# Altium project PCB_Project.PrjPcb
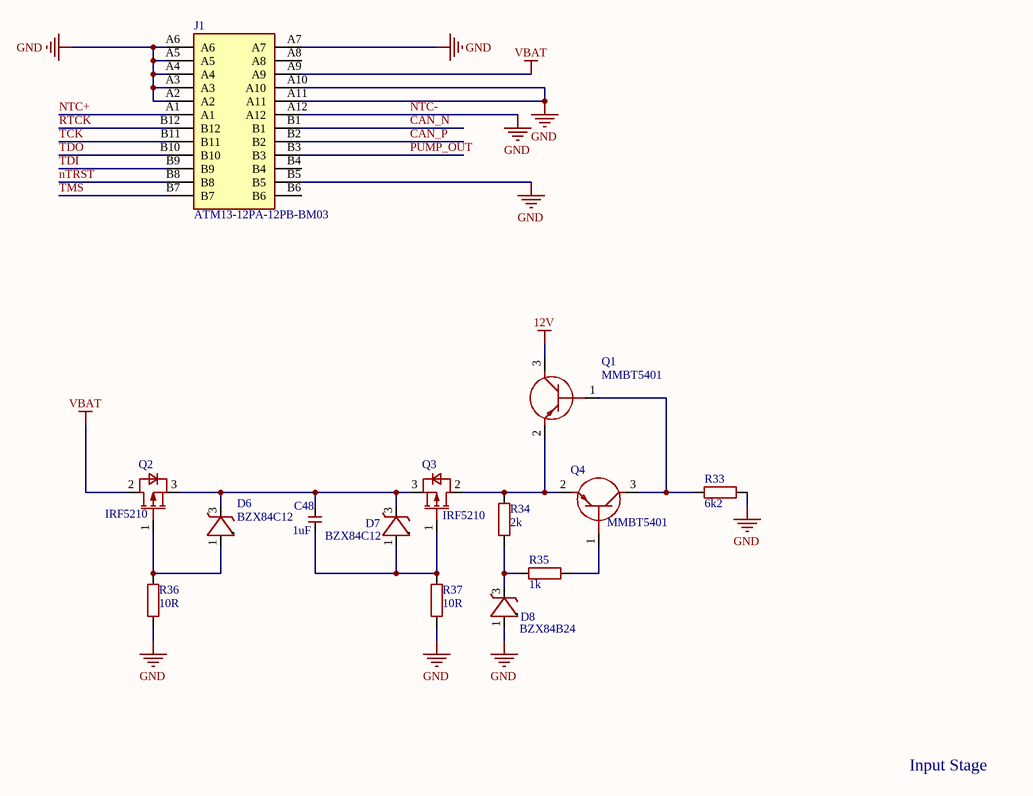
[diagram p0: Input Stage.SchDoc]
6 sheets, 125 parts. Net scope: global (net labels, ports and power ports of the same name join across sheets).
Board file: PCB1.PcbDoc
Sheets:
  Input Stage.SchDoc
  Power Supply.SchDoc
  Microcontroller.SchDoc
  Pump Driver.SchDoc
  Shunt.SchDoc
  NTC.SchDoc

## Sheet Input Stage.SchDoc
size A4; SheetNumber: 1; SheetTotal: 4

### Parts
C48  1uF  [C0402]
D6  BZX84C12  [SOT96P237X111-3N]
D7  BZX84C12  [SOT96P237X111-3N]
D8  BZX84B24  [TRANS_BZX84_ROM-M]
J1  ATM13-12PA-12PB-BM03  [ATM1312PA12PBBM03]
Q1  MMBT5401  [SOT95P240X120-3N]
Q2  IRF5210  [TO254P1528X508-4_3N-V1]
Q3  IRF5210  [TO254P1528X508-4_3N-V1]
Q4  MMBT5401  [SOT95P240X120-3N]
R33  6k2  [R0402]
R34  2k  [R0402]
R35  1k  [R0402]
R36  10R  [R0402]
R37  10R  [R0402]

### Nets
12V: Q1.3(C)
GND: D8.1(A) J1.A2 J1.A3 J1.A4 J1.A5 J1.A6 J1.A7 J1.A10 J1.A11 J1.A12 J1.B5 R33.2 R36.1 R37.1
VBAT: J1.A9 Q2.2(DRAIN)
CAN_N: J1.B1
CAN_P: J1.B2
NTC+: J1.A1
nTRST: J1.B8
PUMP_OUT: J1.B3
RTCK: J1.B12
TCK: J1.B11
TDI: J1.B9
TDO: J1.B10
TMS: J1.B7
NetC48_1: C48.1 D7.1(A) Q3.1(GATE) R37.2
NetC48_2: C48.2 D6.3(K) D7.3(K) Q2.3(SOURCE) Q3.3(SOURCE)
NetD6_1: D6.1(A) Q2.1(GATE) R36.2
NetD8_3: D8.3(K) R34.1 R35.1
NetQ1_1: Q1.1(B) Q4.3(C) R33.1
NetQ1_2: Q1.2(E) Q3.2(DRAIN) Q4.2(E) R34.2
NetQ4_1: Q4.1(B) R35.2

Not connected (* = marked no-connect by the designer): D6 2(NC); D7 2(NC); D8 2(NC); J1 A8 B4 B6

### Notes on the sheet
- NTC-
- Input Stage

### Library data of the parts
C48 = C0402C105K4PAC7411: Ceramic Capacitor, Multilayer, Ceramic, 16V, 10% +Tol, 10% -Tol, X5R, 15% TC, 1uF, Surface Mount, 0402; Manufacturer: KEMET; Multilayer: Yes
D6 D7 = BZX84C12LT1G: Zener Diode, 12V V(Z), 5.39%, 0.25W, Silicon, Unidirectional, TO-236AB; Manufacturer: ON Semiconductor; Package Body Material: Plastic; Dynamic Impedance-Max: 25R; Number of Elements: 1; Max Power Dissipation: 250mW; Test Current: 5mA; Additional Feature: UL RECOGNIZED; Time @ Peak Reflow Temperature-Max (s): 40s; Qualification Status: Not Qualified
D8 = BZX84B24VLFHT116: Zener Diode, 24V V(Z), 2.08%, 0.25W, Silicon, Unidirectional
J1 = ATM13-12PA-12PB-BM03: AMPHENOL SINE/TUCHEL - ATM13-12PA-12PB-BM03 - ATM HEADER  (2) 12 POSITION SIZE 20, A&B KEY  - TIN PLATING 98AC7190; Geometry.Height: 35.4mm
Q1 Q4 = MMBT5401: Small Signal Bipolar Transistor, 0.6A I(C), 150V V(BR)CEO, 1-Element, PNP, Silicon, TO-236; Manufacturer: Diotec; Package Body Material: Plastic; Max Collector Current: 600mA; DC Current Gain-Min (hFE): 50; Number of Elements: 1; Frequency: 100MHz; Qualification Status: Not Qualified
Q2 Q3 = IRF5210STRLPBF: Zener Diode, 24V V(Z), 2.08%, 0.25W, Silicon, Unidirectional; Manufacturer: Infineon; Package Body Material: Plastic; Polarity/Channel Type: P-CHANNEL; Avalanche Energy Rating (Eas): 120mJ; Case Connection: DRAIN; Drain Current-Max (ID): 38A; Drain-source On Resistance-Max: 60mR; DS Breakdown Voltage-Min: 100V; FET Technology: METAL-OXIDE SEMICONDUCTOR; Number of Elements: 1; Operating Mode: ENHANCEMENT MODE; Pulsed Drain Current-Max (IDM): 140A; Transistor Application: SWITCHING; Time @ Peak Reflow Temperature-Max (s): 30s; Power Dissipation-Max (Abs): 170W; JEDEC-95 Code: TO-263AB; Qualification Status: Not Qualified
R33 = AC0402FR-076K2L: Fixed Resistor, Metal Glaze/thick Film, 0.0625W, 6200ohm, 50V, 1% +/-Tol, 100ppm/Cel, Surface Mount, 0402; Manufacturer: Yageo; Additional Feature: LASER TRIMMABLE; Power: 62.5mW; Rated Temperature: 70°C; Value: 6.2kR; Temperature Coefficient (ppm/Cel): 100; Package Height: 0.32mm; Package Length: 1mm; Package Width: 0.5mm; Reference Standard: AEC-Q200
R34 = RC0402JR-072KP: Fixed Resistor, Metal Glaze/thick Film, 0.0625W, 2000ohm, 50V, 5% +/-Tol, 150ppm/Cel, Surface Mount, 0402; Manufacturer: Yageo
R35 = RT0402FRE101KL: Fixed Resistor, Thin Film, 0.0625W, 1000ohm, 50V, 1% +/-Tol, 50ppm/Cel, Surface Mount, 0402; Manufacturer: Yageo
R36 R37 = AC0402FR-1010RL: Fixed Resistor, Metal Glaze/thick Film, 0.0625W, 10ohm, 50V, 1% +/-Tol, 200ppm/Cel, Surface Mount, 0402; Manufacturer: Yageo; Additional Feature: LASER TRIMMABLE; Power: 62.5mW; Rated Temperature: 70°C; Temperature Coefficient (ppm/Cel): 200; Package Height: 0.32mm; Package Length: 1mm; Package Width: 0.5mm; Reference Standard: AEC-Q200

## Sheet Power Supply.SchDoc
size A4; SheetNumber: 2; SheetTotal: 4
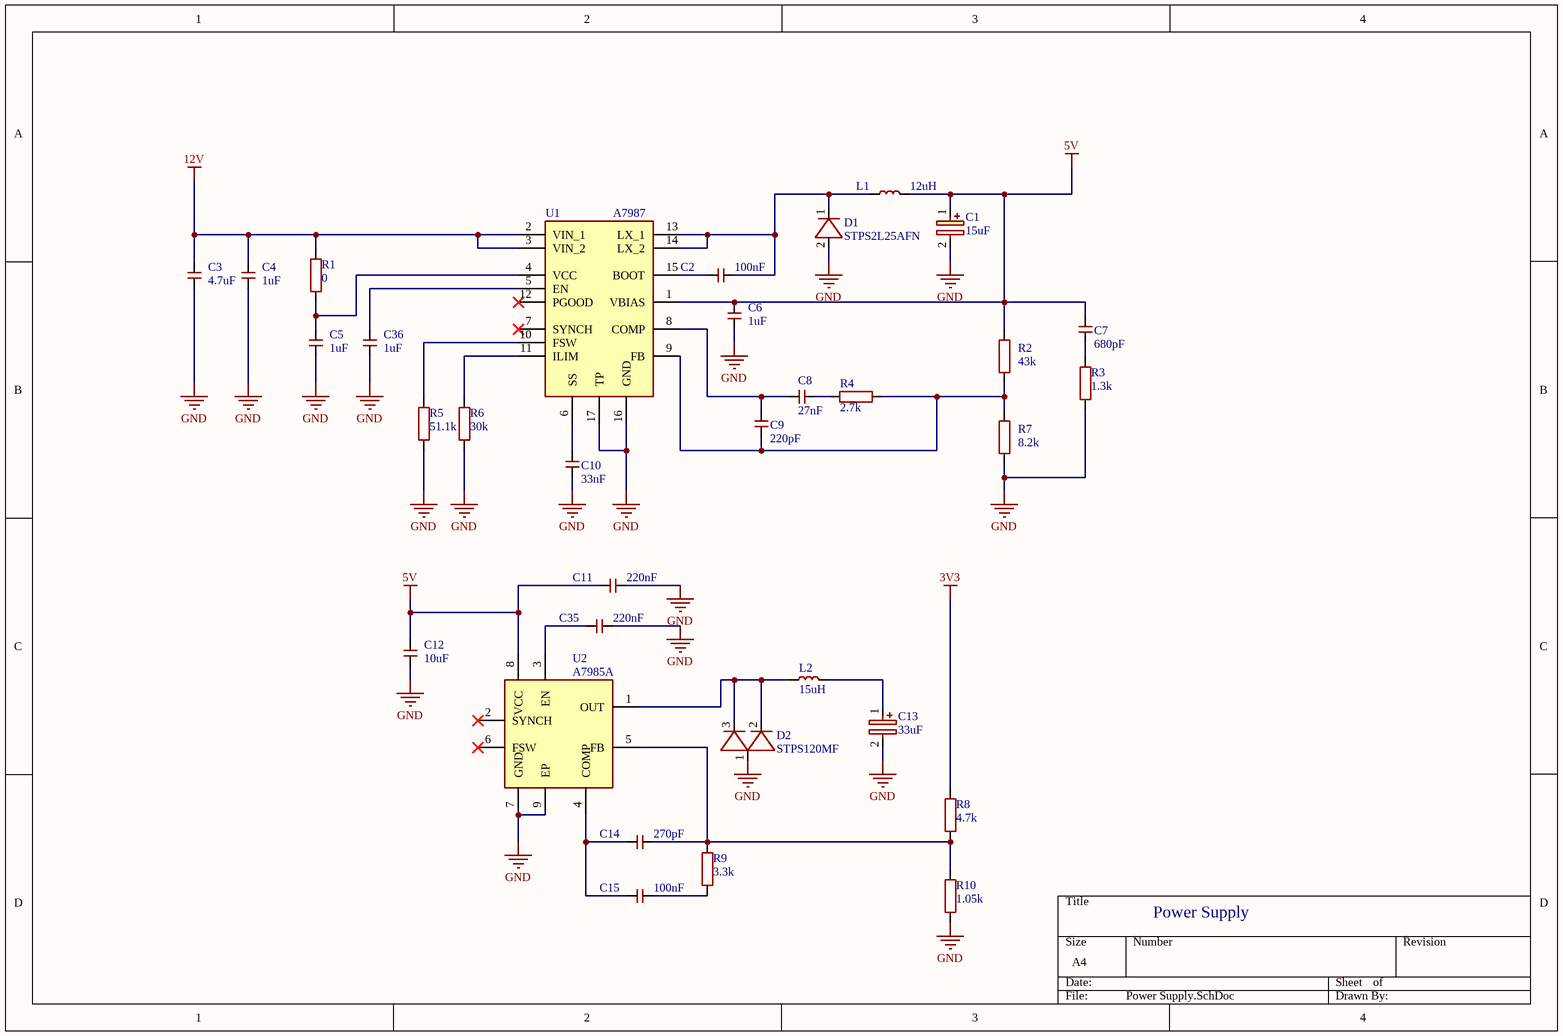
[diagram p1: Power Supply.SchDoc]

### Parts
C1  15uF  [CAPAE660X850N]
C2  100nF  [C0402]
C3  4.7uF  [CAPC3216X180N]
C4  1uF  [C0402]
C5  1uF  [C0402]
C6  1uF  [C0402]
C7  680pF  [C0402]
C8  27nF  [C0402]
C9  220pF  [C0402]
C10  33nF  [C0402]
C11  220nF  [C0402]
C12  10uF  [CAPC2012X145N]
C13  33uF  [10SVPS10M]
C14  270pF  [C0402]
C15  100nF  [C0402]
C35  220nF  [C0402]
C36  1uF  [C0402]
D1  STPS2L25AFN  [SODFL5226X110N]
D2  STPS120MF  [STPS120MF]
L1  12uH  [WE-PD2_105455]
L2  15uH  [INDPM6868X420N]
R1  0  [R0402]
R2  43k  [R0402]
R3  1.3k  [R0402]
R4  2.7k  [R0402]
R5  51.1k  [R0402]
R6  30k  [R0402]
R7  8.2k  [R0402]
R8  4.7k  [R0402]
R9  3.3k  [R0402]
R10  1.05k  [R0402]
U1  A7987  [SOP65P640X120-17N]
U2  A7985A  [SOIC127P600X170-9N]

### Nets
3V3: R8.2
5V: C1.1(+) C6.1 C7.2 C11.1 C12.2 L1.2 R2.2 U1.1(VBIAS) U2.8(VCC)
12V: C3.2 C4.2 R1.2 U1.2(VIN_1) U1.3(VIN_2)
GND: C1.2 C3.1 C4.1 C5.1 C6.2 C10.1 C11.2 C12.1 C13.2 C35.2 C36.1 D1.2(A) D2.1(A) R3.1 R5.1 R6.1 R7.1 R10.1 U1.16(GND) U1.17(TP) U2.7(GND) U2.9(EP)
NetC2_1: C2.1 U1.15(BOOT)
NetC2_2: C2.2 D1.1(K) L1.1 U1.13(LX_1) U1.14(LX_2)
NetC5_2: C5.2 R1.1 U1.4(VCC)
NetC7_1: C7.1 R3.2
NetC8_1: C8.1 C9.2 U1.8(COMP)
NetC8_2: C8.2 R4.1
NetC9_1: C9.1 R2.1 R4.2 R7.2 U1.9(FB)
NetC10_2: C10.2 U1.6(SS)
NetC13_1: C13.1(+) L2.2
NetC14_1: C14.1 C15.1 U2.4(COMP)
NetC14_2: C14.2 R8.1 R9.2 R10.2 U2.5(FB)
NetC15_2: C15.2 R9.1
NetC35_1: C35.1 U2.3(EN)
NetC36_2: C36.2 U1.5(EN)
NetD2_2: D2.2(K) D2.3(K) L2.1 U2.1(OUT)
NetR5_2: R5.2 U1.10(FSW)
NetR6_2: R6.2 U1.11(ILIM)

Not connected (* = marked no-connect by the designer): U1 7(SYNCH)* 12(PGOOD)*; U2 2(SYNCH)* 6(FSW)*

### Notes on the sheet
- Power Supply

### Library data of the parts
C1 = AHA0608150M050R: Hybrid Aluminum V-Chip, 15uF, 50V ¦ AVX AHA0608150M050R; Manufacturer: Kyocera AVX
C2 C15 = C0402C104K3PACTU: Ceramic Capacitor, Multilayer, Ceramic, 25V, 10% +Tol, 10% -Tol, X5R, 15% TC, 0.1uF, Surface Mount, 0402; Manufacturer: KEMET; Multilayer: Yes
C3 = EMK316BJ475MLHT: Ceramic Capacitor, Multilayer, Ceramic, 16V, 20% +Tol, 20% -Tol, X5R, 15% TC, 4.7uF, Surface Mount, 1206; Manufacturer: Taiyo Yuden
C4-C6 C36 = C0402C105K4PAC7411: as C48 on sheet Input Stage
C7 = C0402C681K8RACTU: Ceramic Capacitor, Multilayer, Ceramic, 10V, 10% +Tol, 10% -Tol, X7R, 15% TC, 0.00068uF, Surface Mount, 0402; Manufacturer: KEMET; Multilayer: Yes
C8 = C0402C273K4RALTU: .027Uf 16.0V Rohs Compliant: No; Manufacturer: KEMET
C9 = C0402S221K5RACAUTO: Ceramic Capacitor, Multilayer, Ceramic, 50V, 10% +Tol, 10% -Tol, X7R, 15% TC, 0.00022uF, Surface Mount, 0402; Manufacturer: KEMET
C10 = C0402C333M4REC7411: Ceramic Capacitor, Multilayer, Ceramic, 16V, 20% +Tol, 20% -Tol, X7R, 15% TC, 0.033uF, Surface Mount, 0402; Manufacturer: KEMET
C11 C35 = C0402C224K9PAC7411: Ceramic Capacitor, Multilayer, Ceramic, 6.3V, 10% +Tol, 10% -Tol, X5R, 15% TC, 0.22uF, Surface Mount, 0402; Manufacturer: KEMET; Multilayer: Yes
C12 = GRM21BR60J106KE19L: Ceramic Capacitor, Multilayer, Ceramic, 6.3V, 10% +Tol, 10% -Tol, X5R, 15% TC, 10uF, Surface Mount, 0805; Manufacturer: Murata; Multilayer: Yes
C13 = 4SVP33M: Aluminum Electrolytic Capacitor, Polarized, Aluminum (solid Polymer), 4V, 20% +Tol, 20% -Tol, 33uF, Surface Mount, 1717; Manufacturer: Panasonic; Manufacturer Series: SVP; Dielectric Material: Aluminium; ESR (Equivalent Series Resistance): 200mR; Leakage Current: 66uA; Ripple Current: 37mA; Tan Delta: 0.15
C14 = C0402C271J5GAC7411: Ceramic Capacitor, Multilayer, Ceramic, 50V, 5% +Tol, 5% -Tol, C0G, 30ppm/Cel TC, 0.00027uF, Surface Mount, 0402; Manufacturer: KEMET; Multilayer: Yes
D1 = STPS2L25AFN: Rectifier Diode; Manufacturer: STMicroelectronics
D2 = STPS120MF: Rectifier Diode, Schottky, 1 Phase, 1 Element, 1A, 20V V(RRM), Silicon, DO-222AA; Manufacturer: STMicroelectronics; Package Body Material: Plastic; Case Connection: CATHODE; Forward Voltage: 410mV; Non-rep Pk Forward Current-Max: 50A; Number of Elements: 1; Qualification Status: Not Qualified
L1 = 744776112: General Purpose Inductor, 12uH, 20%, 1 Element, Nickel-zinc Ferrite-Core, SMD, 3935; Manufacturer: Wurth Electronics; DC Resistance (DCR): 70mR; Inductor Application: POWER INDUCTOR; Channels: 1; Max Current Rating: 2.72A; Shape/Size Description: RECTANGULAR PACKAGE; Shielding: Unshielded; Test Frequency: 1kHz; Self Resonant Frequency: 20MHz
L2 = SRR6838A-150M: Power Inductors - SMD Ind,6.8x6.8x3.8mm,15uH+/-20%,2.1A,; Manufacturer: Bourns
R1 = AC0402JR-7D0RL: Fixed Resistor, Metal Glaze/thick Film, 0.0625W, 0ohm, Surface Mount, 0402; Manufacturer: Yageo
R2 = AF0402FR-0743KL: Fixed Resistor, Metal Glaze/thick Film, 0.0625W, 43000ohm, 50V, 1% +/-Tol, 100ppm/Cel, Surface Mount, 0402; Manufacturer: Yageo; Additional Feature: ANTI-SULFUR; Power: 62.5mW; Rated Temperature: 70°C; Value: 43kR; Temperature Coefficient (ppm/Cel): 100; Package Height: 0.32mm; Package Length: 1mm; Package Width: 0.5mm; Reference Standard: AEC-Q200
R3 = AT0402DRD071K3L: Fixed Resistor, Thin Film, 0.0625W, 1300ohm, 50V, 0.5% +/-Tol, 25ppm/Cel, Surface Mount, 0402; Manufacturer: Yageo; Additional Feature: HIGH PRECISION; Power: 62.5mW; Rated Temperature: 70°C; Value: 1.3kR; Temperature Coefficient (ppm/Cel): 25; Package Height: 0.3mm; Package Length: 1mm; Package Width: 0.5mm; Reference Standard: AEC-Q200
R4 = AC0402FR-072K7L: Fixed Resistor, Metal Glaze/thick Film, 0.0625W, 2700ohm, 50V, 1% +/-Tol, 100ppm/Cel, Surface Mount, 0402; Manufacturer: Yageo; Additional Feature: LASER TRIMMABLE; Power: 62.5mW; Rated Temperature: 70°C; Value: 2.7kR; Temperature Coefficient (ppm/Cel): 100; Package Height: 0.32mm; Package Length: 1mm; Package Width: 0.5mm; Reference Standard: AEC-Q200
R5 = RT0402BRE0751K1L: Fixed Resistor, Thin Film, 0.0625W, 51100ohm, 50V, 0.1% +/-Tol, 50ppm/Cel, Surface Mount, 0402; Manufacturer: Yageo; Additional Feature: HIGH PRECISION; Power: 62.5mW; Rated Temperature: 70°C; Value: 51.1kR; Temperature Coefficient (ppm/Cel): 50; Package Height: 0.3mm; Package Length: 1mm; Package Width: 0.5mm
R6 = RC0402FR-1330KL: Fixed Resistor, Metal Glaze/thick Film, 0.0625W, 30000ohm, 50V, 1% +/-Tol, 100ppm/Cel, Surface Mount, 0402; Manufacturer: Yageo; Additional Feature: LASER TRIMMABLE; Power: 62.5mW; Rated Temperature: 70°C; Value: 30kR; Temperature Coefficient (ppm/Cel): 100; Package Height: 0.35mm; Package Length: 1mm; Package Width: 0.5mm
R7 = RC0402BR-078K2L: Fixed Resistor, Metal Glaze/thick Film, 0.0625W, 8200ohm, 50V, 0.1% +/-Tol, 100ppm/Cel, Surface Mount, 0402; Manufacturer: Yageo
R8 = RC0402FR-7W4K7L: Fixed Resistor, Metal Glaze/thick Film, 0.125W, 4700ohm, 50V, 1% +/-Tol, 200ppm/Cel, Surface Mount, 0402; Manufacturer: Yageo; Additional Feature: LASER TRIMMABLE; Power: 125mW; Rated Temperature: 70°C; Value: 4.7kR; Temperature Coefficient (ppm/Cel): 200; Package Height: 0.35mm; Package Length: 1mm; Package Width: 0.5mm
R9 = RC0402FR-7D3K3L: Fixed Resistor, Metal Glaze/thick Film, 0.0625W, 3300ohm, 50V, 1% +/-Tol, 100ppm/Cel, Surface Mount, 0402; Manufacturer: Yageo; Additional Feature: LASER TRIMMABLE; Power: 62.5mW; Rated Temperature: 70°C; Value: 3.3kR; Temperature Coefficient (ppm/Cel): 100; Package Height: 0.35mm; Package Length: 1mm; Package Width: 0.5mm
R10 = AC0402FR-071K05L: Fixed Resistor, Metal Glaze/thick Film, 0.0625W, 1050ohm, 50V, 1% +/-Tol, 100ppm/Cel, Surface Mount, 0402; Manufacturer: Yageo; Additional Feature: LASER TRIMMABLE; Power: 62.5mW; Rated Temperature: 70°C; Value: 1.05kR; Temperature Coefficient (ppm/Cel): 100; Package Height: 0.32mm; Package Length: 1mm; Package Width: 0.5mm; Reference Standard: AEC-Q200
U1 = A7987TR: Switching Regulator, Voltage-mode, 4.4A, 1650kHz Switching Freq-Max, PDSO16; Manufacturer: STMicroelectronics
U2 = A7985ATR: Switching Regulator, Voltage-mode, 3.5A, 275kHz Switching Freq-Max, PDSO8; Manufacturer: STMicroelectronics; Package Body Material: Plastic; Package Equivalence Code: SOP8,.25; Control Technique: PULSE WIDTH MODULATION; Max Supply Voltage: 38V; Min Input Voltage: 4.5V; Nominal Supply Voltage: 12V; Channels: 1; Switcher Configuration: BUCK; Qualification Status: Not Qualified

## Sheet Microcontroller.SchDoc
size A4; SheetNumber: 3; SheetTotal: 4
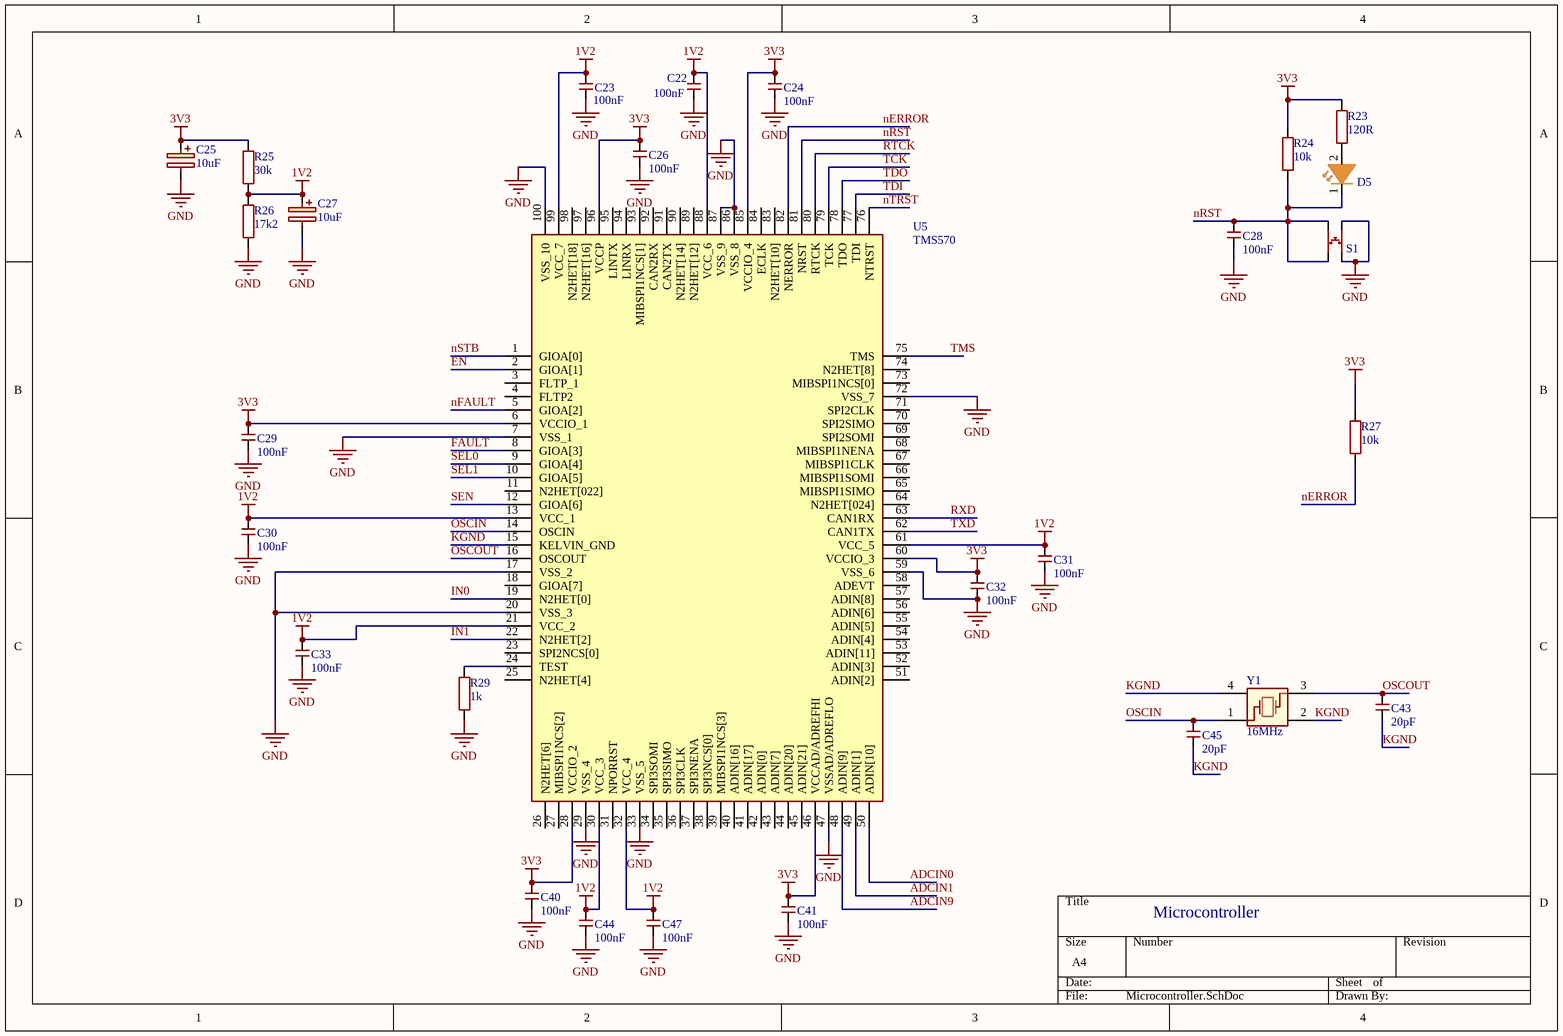
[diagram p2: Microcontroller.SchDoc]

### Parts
C22  100nF  [C0402]
C23  100nF  [C0402]
C24  100nF  [C0402]
C25  10uF  [CAPAE660X565N]
C26  100nF  [C0402]
C27  10uF  [CAPAE660X565N]
C28  100nF  [C0402]
C29  100nF  [C0402]
C30  100nF  [C0402]
C31  100nF  [C0402]
C32  100nF  [C0402]
C33  100nF  [C0402]
C40  100nF  [C0402]
C41  100nF  [C0402]
C43  20pF  [C0402]
C44  100nF  [C0402]
C45  20pF  [C0402]
C47  100nF  [C0402]
D5  150060AS75000  [LED-0603]  (value not drawn)
R23  120R  [R0402]
R24  10k  [R0402]
R25  30k  [R0402]
R26  17k2  [R0402]
R27  10k  [R0402]
R29  1k  [R0402]
S1  Pushbutton  [Pushbutton]  (value not drawn)
U5  TMS570  [QFP50P1600X1600X160-100N]
Y1  16MHz  [ECS1601037B2CTNTR]

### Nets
1V2: C22.2 C23.2 C27.1(+) C30.2 C31.2 C33.2 C44.2 C47.2 R25.1 R26.2 U5.13(VCC_1) U5.21(VCC_2) U5.30(VCC_3) U5.32(VCC_4) U5.61(VCC_5) U5.88(VCC_6) U5.99(VCC_7)
3V3: C24.2 C25.1(+) C26.2 C29.2 C32.2 C40.2 C41.2 R23.2 R24.2 R25.2 R27.2 U5.6(VCCIO_1) U5.28(VCCIO_2) U5.46(VCCAD/ADREFHI) U5.60(VCCIO_3) U5.85(VCCIO_4) U5.96(VCCP)
GND: C22.1 C23.1 C24.1 C25.2 C26.1 C27.2 C28.1 C29.1 C30.1 C31.1 C32.1 C33.1 C40.1 C41.1 C44.1 C47.1 R26.1 R29.1 S1.1 S1.2 U5.7(VSS_1) U5.17(VSS_2) U5.20(VSS_3) U5.29(VSS_4) U5.33(VSS_5) U5.47(VSSAD/ADREFLO) U5.59(VSS_6) U5.72(VSS_7) U5.86(VSS_8) U5.87(VSS_9) U5.100(VSS_10)
ADCIN0: U5.50(ADIN[10])
ADCIN1: U5.49(ADIN[1])
ADCIN9: U5.48(ADIN[9])
EN: U5.2(GIOA[1])
~{FAULT}: U5.8(GIOA[3])
IN0: U5.19(N2HET[0])
IN1: U5.22(N2HET[2])
KGND: C43.1 C45.1 U5.15(KELVIN_GND) Y1.2 Y1.4
nERROR: R27.1 U5.82(NERROR)
nFAULT: U5.5(GIOA[2])
nRST: C28.2 D5.1(K) R24.1 S1.3 S1.4 U5.81(NRST)
nSTB: U5.1(GIOA[0])
nTRST: U5.76(NTRST)
OSCIN: C45.2 U5.14(OSCIN) Y1.1
OSCOUT: C43.2 U5.16(OSCOUT) Y1.3
RTCK: U5.80(RTCK)
RXD: U5.63(CAN1RX)
SEL0: U5.9(GIOA[4])
SEL1: U5.10(GIOA[5])
SEN: U5.12(GIOA[6])
TCK: U5.79(TCK)
TDI: U5.77(TDI)
TDO: U5.78(TDO)
TMS: U5.75(TMS)
TXD: U5.62(CAN1TX)
NetD5_2: D5.2(A) R23.1
NetR29_2: R29.2 U5.24(TEST)

Not connected (* = marked no-connect by the designer): U5 3(FLTP_1) 4(FLTP2) 11(N2HET[022]) 18(GIOA[7]) 23(SPI2NCS[0]) 25(N2HET[4]) 26(N2HET[6]) 27(MIBSPI1NCS[2]) 31(NPORRST) 34(SPI3SOMI) 35(SPI3SIMO) 36(SPI3CLK) 37(SPI3NENA) 38(SPI3NCS[0]) 39(MIBSPI1NCS[3]) 40(ADIN[16]) 41(ADIN[17]) 42(ADIN[0]) 43(ADIN[7]) 44(ADIN[20]) 45(ADIN[21]) 51(ADIN[2]) 52(ADIN[3]) 53(ADIN[11]) 54(ADIN[4]) 55(ADIN[5]) 56(ADIN[6]) 57(ADIN[8]) 58(ADEVT) 64(N2HET[024]) 65(MIBSPI1SIMO) 66(MIBSPI1SOMI) 67(MIBSPI1CLK) 68(MIBSPI1NENA) 69(SPI2SOMI) 70(SPI2SIMO) 71(SPI2CLK) 73(MIBSPI1NCS[0]) 74(N2HET[8]) 83(N2HET[10]) 84(ECLK) 89(N2HET[12]) 90(N2HET[14]) 91(CAN2TX) 92(CAN2RX) 93(MIBSPI1NCS[1]) 94(LINRX) 95(LINTX) 97(N2HET[16]) 98(N2HET[18])

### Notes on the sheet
- Microcontroller

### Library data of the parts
C22-C24 C26 C28-C33 C40 C41 C44 C47 = C0402C104K3PACTU: as C2 on sheet Power Supply
C25 C27 = EXV106M050A9GAA: Aluminum Electrolytic Capacitor, Polarized, Aluminum (wet), 50V, 20% +Tol, 20% -Tol, 10uF, Surface Mount, 2626; Manufacturer: KEMET; Dielectric Material: Aluminium; ESR (Equivalent Series Resistance): 2.6R; Leakage Current: 5uA; Ripple Current: 98mA; Tan Delta: 0.12
C43 C45 = C0402C200F5GACTU: Ceramic Capacitor, Multilayer, Ceramic, 50V, 1% +Tol, 1% -Tol, C0G, 30ppm/Cel TC, 0.00002uF, Surface Mount, 0402; Manufacturer: KEMET; Multilayer: Yes
D5 = 150060AS75000: Single Color LED, Amber, Water Clear, 1.1mm; Manufacturer: Wurth Electronics
R23 = AC0402FR-7D120RL: Fixed Resistor, Metal Glaze/thick Film, 0.0625W, 120ohm, 50V, 1% +/-Tol, -100,100ppm/Cel, 0402; Manufacturer: Yageo; Power: 62.5mW; Package Height: 0.32mm; Package Length: 1mm; Package Width: 0.5mm; Reference Standard: AEC-Q200
R24 R27 = RP0402BRD0710KL: Resistor, 10K, 0.1%, 0.063W, THIN FILM, 0402;; Manufacturer: Yageo
R25 = RC0402FR-1330KL: as R6 on sheet Power Supply
R26 = TNPW040217K2BEED: Fixed Resistor, Thin Film, 0.063W, 17200ohm, 50V, 0.1% +/-Tol, 25ppm/Cel, Surface Mount, 0402; Manufacturer: Vishay Dale; Manufacturer Series: TNPW; Power: 63mW; Rated Temperature: 70°C; Value: 17.2kR; Temperature Coefficient (ppm/Cel): 25
R29 = RT0402FRE101KL: as R35 on sheet Input Stage
S1 = Pushbutton: BUTON MINI 6X6X5, 4 PINI
U5 = TMS5700332BPZQQ1: RISC Microcontroller, 32-Bit, FLASH, CORTEX-R4F CPU, 80MHz, CMOS, PQFP100; Manufacturer: Texas Instruments
Y1 = ECS-160-10-37B2-CTN-TR: Crystal 16MHz 10pF 4-Pin SMD ECX-1637B2 T/R; Manufacturer: ECS International

## Sheet Pump Driver.SchDoc
size A4; SheetNumber: 4; SheetTotal: 4
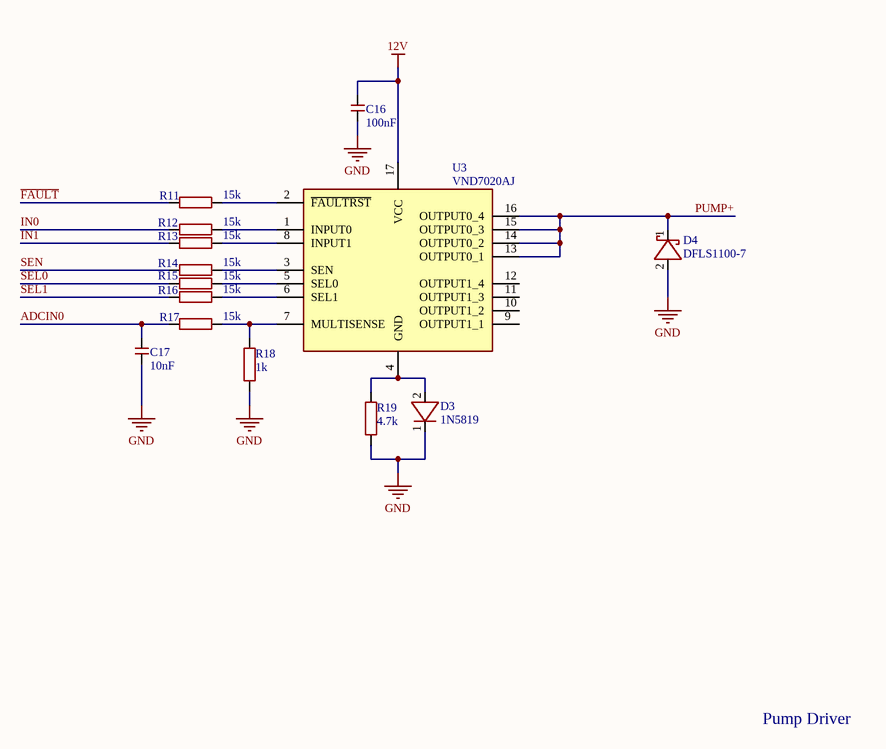
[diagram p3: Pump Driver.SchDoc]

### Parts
C16  100nF  [C0402]
C17  10nF  [C0402]
D3  1N5819  [SOD3716X125N]
D4  DFLS1100-7  [DFLS110]
R11  15k  [R0402]
R12  15k  [R0402]
R13  15k  [R0402]
R14  15k  [R0402]
R15  15k  [R0402]
R16  15k  [R0402]
R17  15k  [R0402]
R18  1k  [R0402]
R19  4.7k  [R0402]
U3  VND7020AJ  [SOP50P600X170-17N]

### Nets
12V: C16.2 U3.17(VCC)
GND: C16.1 C17.1 D3.1(K) D4.2(A) R18.1 R19.1
ADCIN0: C17.2 R17.1
~{FAULT}: R11.1
IN0: R12.1
IN1: R13.1
PUMP+: D4.1(K) U3.13(OUTPUT0_1) U3.14(OUTPUT0_2) U3.15(OUTPUT0_3) U3.16(OUTPUT0_4)
SEL0: R15.1
SEL1: R16.1
SEN: R14.1
NetD3_2: D3.2(A) R19.2 U3.4(GND)
NetR11_2: R11.2 U3.2(~{FAULTRST})
NetR12_2: R12.2 U3.1(INPUT0)
NetR13_2: R13.2 U3.8(INPUT1)
NetR14_2: R14.2 U3.3(SEN)
NetR15_2: R15.2 U3.5(SEL0)
NetR16_2: R16.2 U3.6(SEL1)
NetR17_2: R17.2 R18.2 U3.7(MULTISENSE)

Not connected (* = marked no-connect by the designer): U3 9(OUTPUT1_1) 10(OUTPUT1_2) 11(OUTPUT1_3) 12(OUTPUT1_4)

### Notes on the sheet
- Pump Driver

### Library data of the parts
C16 = C0402C104K3PACTU: as C2 on sheet Power Supply
C17 = C0402T103K4RALTU: Ceramic Capacitor, Multilayer, Ceramic, 16V, 10% +Tol, 10% -Tol, X7R, 15% TC, 0.01uF, Surface Mount, 0402; Manufacturer: KEMET; Multilayer: Yes
D3 = 1N5819HW-7-F: Rectifier Diode, Schottky, 1 Phase, 1 Element, 1A, 40V V(RRM), Silicon; Manufacturer: Diodes; Package Body Material: Plastic; Number of Elements: 1; Max Power Dissipation: 450mW; Forward Voltage: 320mV; Non-rep Pk Forward Current-Max: 25A; Time @ Peak Reflow Temperature-Max (s): 40s; Qualification Status: Not Qualified
D4 = DFLS1100-7: Rectifier Diode, Schottky, 1 Phase, 1 Element, 1A, 100V V(RRM), Silicon; Manufacturer: Diodes; Package Body Material: Plastic; Case Connection: CATHODE; Forward Voltage: 770mV; Non-rep Pk Forward Current-Max: 40A; Number of Elements: 1; Time @ Peak Reflow Temperature-Max (s): 40s; Qualification Status: Not Qualified
R11-R17 = AC0402JR-7W15KL: Chip Resistor Automotive Grade Thick Film 0402 15kOhm 5% Paper T/R; Manufacturer: Yageo
R18 = RT0402FRE101KL: as R35 on sheet Input Stage
R19 = RC0402FR-7W4K7L: as R8 on sheet Power Supply
U3 = VND7020AJTR: Buffer/Inverter Based Peripheral Driver, PDSO16; Manufacturer: STMicroelectronics; Package Body Material: Plastic; Built-in Protections: Over Current,Over Voltage,Under Voltage,TRANSIENT,THERMAL; Interface IC Type: BUFFER OR INVERTER BASED PERIPHERAL DRIVER; Channels: 1; Output Current Flow Direction: SINK; Max Supply Voltage: 28V; Min Supply Voltage: 4V; Nominal Supply Voltage: 13V; Turn-Off Delay Time: 100us; Turn-On Delay Time: 120us

## Sheet Shunt.SchDoc
size A4; SheetNumber: 5; SheetTotal: 5
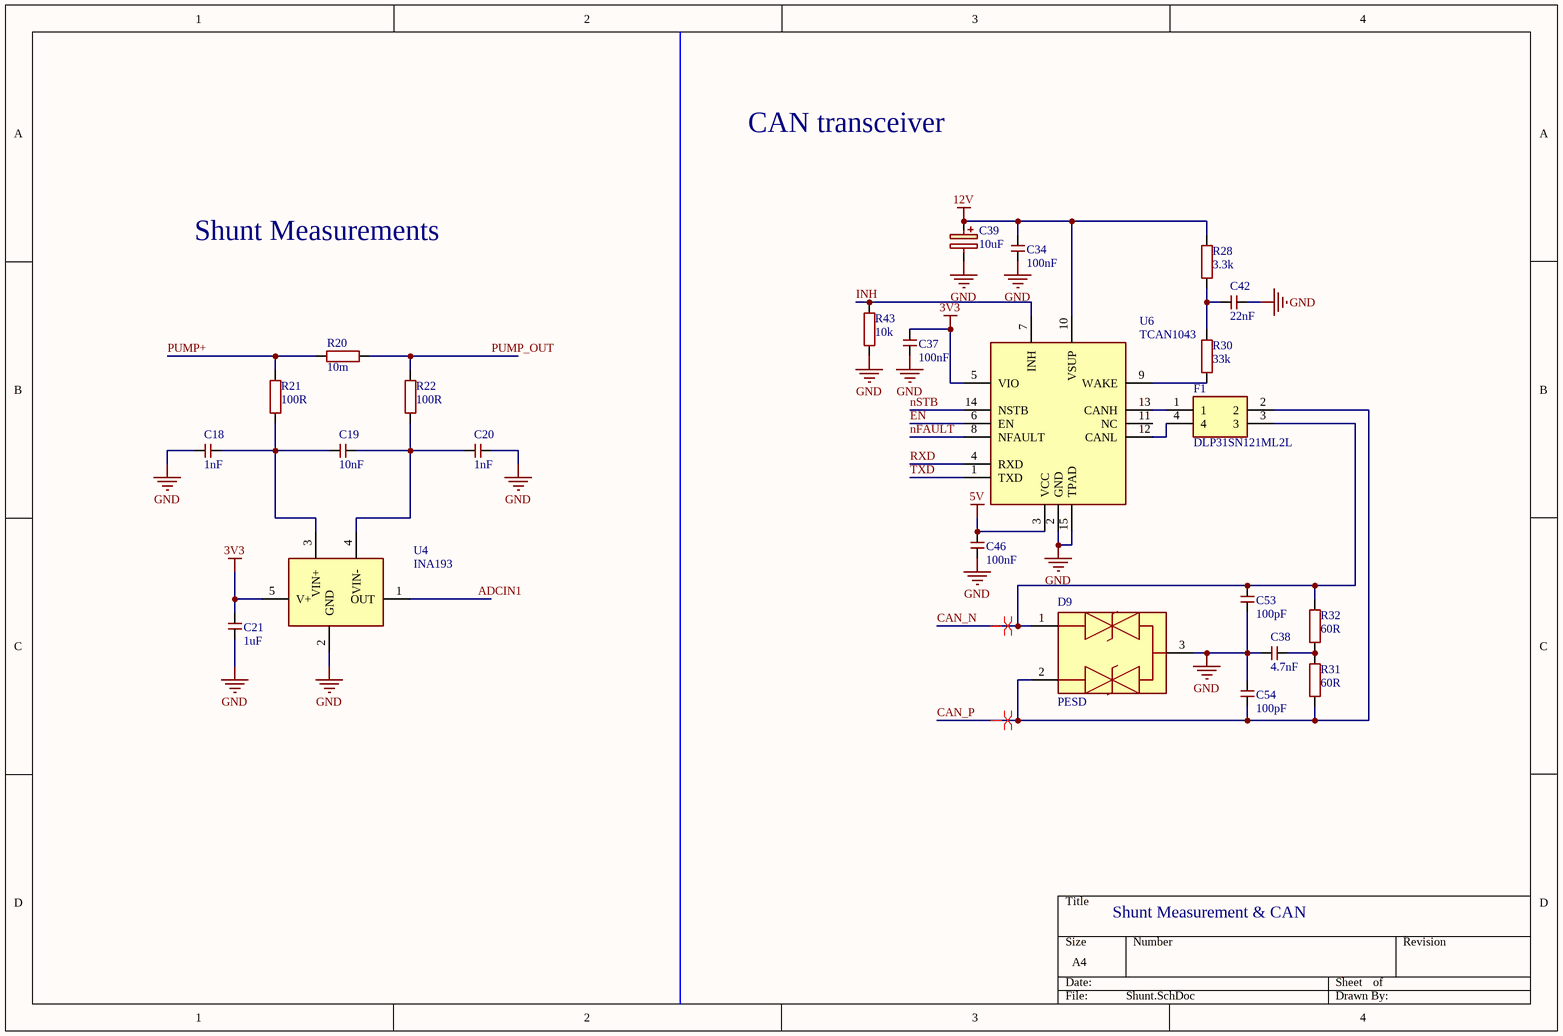
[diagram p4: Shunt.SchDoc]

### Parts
C18  1nF  [C0402]
C19  10nF  [C0402]
C20  1nF  [C0402]
C21  1uF  [C0402]
C34  100nF  [C0402]
C37  100nF  [C0402]
C38  4.7nF  [C0402]
C39  10uF  [CAPAE660X565N]
C42  22nF  [C0402]
C46  100nF  [C0402]
C53  100pF  [C0402]
C54  100pF  [C0402]
D9  PESD  [PESD2CANFD36LTQR]
F1  DLP31SN121ML2L  [DLP31SN121ML2B]
R20  10m  [CSS0402FT10L0]
R21  100R  [R0402]
R22  100R  [R0402]
R28  3.3k  [R0402]
R30  33k  [R0402]
R31  60R  [R0201]
R32  60R  [R0201]
R43  10k  [R0402]
U4  INA193  [SOT95P280X145-5N]
U6  TCAN1043  [SON65P300X450X90-15N]

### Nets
3V3: C21.2 C37.2 U4.5(V+) U6.5(VIO)
5V: C46.2 U6.3(VCC)
12V: C34.2 C39.1(+) R28.2 U6.10(VSUP)
GND: C18.1 C20.2 C21.1 C34.1 C37.1 C38.2 C39.2 C42.1 C46.1 C53.2 C54.1 D9.3(CC) R43.1 U4.2(GND) U6.2(GND) U6.15(TPAD)
ADCIN1: U4.1(OUT)
CAN_N: C53.1 D9.1(K1) F1.3 R32.1
CAN_P: C54.2 D9.2(K2) F1.2 R31.2
EN: U6.6(EN)
INH: R43.2 U6.7(INH)
nFAULT: U6.8(NFAULT)
nSTB: U6.14(NSTB)
PUMP+: R20.1 R21.2
PUMP_OUT: R20.2 R22.2
RXD: U6.4(RXD)
TXD: U6.1(TXD)
NetC18_2: C18.2 C19.1 R21.1 U4.3(VIN+)
NetC19_2: C19.2 C20.1 R22.1 U4.4(VIN-)
NetC38_1: C38.1 R31.1 R32.2
NetC42_2: C42.2 R28.1 R30.2
NetF1_1: F1.1 U6.13(CANH)
NetF1_4: F1.4 U6.12(CANL)
NetR30_1: R30.1 U6.9(WAKE)

Not connected (* = marked no-connect by the designer): U6 11(NC)

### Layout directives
differential pair: CAN_N, CAN_P

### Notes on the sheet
- CAN transceiver
- Shunt Measurements
- Shunt Measurement & CAN

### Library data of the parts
C18 C20 = C0402C102J5GACAUTO: Ceramic Capacitor, Multilayer, Ceramic, 50V, 5% +Tol, 5% -Tol, C0G, 30ppm/Cel TC, 0.001uF, Surface Mount, 0402; Manufacturer: KEMET; Multilayer: Yes; Reference Standard: AEC-Q200
C19 = C0402T103K4RALTU: as C17 on sheet Pump Driver
C21 = C0402C105K4PAC7411: as C48 on sheet Input Stage
C34 C37 C46 = C0402C104K3PACTU: as C2 on sheet Power Supply
C38 = C0402C472J4JACAUTO: Cap Ceramic 0.0047uF 16V U2J 5% Pad SMD 0402 125C T/R; Manufacturer: KEMET
C39 = EXV106M050A9GAA: as C25 on sheet Microcontroller
C42 = C0402C223J5RACTU: Ceramic Capacitor, Multilayer, Ceramic, 50V, 5% +Tol, 5% -Tol, X7R, 15% TC, 0.022uF, Surface Mount, 0402; Manufacturer: KEMET; Multilayer: Yes
C53 C54 = C0402C101K3RACAUTO: Multilayer Ceramic Capacitors MLCC - SMD/SMT 25V 100pF X7R 0402 10% AEC-Q200; Manufacturer: KEMET
D9 = PESD2CANFD36LT-QR: ESD Protection Diodes / TVS Diodes ESD protection for in-vehicle networks; Manufacturer: Nexperia
F1 = DLP31SN121ML2L: Data Line Filter, 2 Function(s), 16V, 0.1A, 4 Pin(s); Manufacturer: Murata; DC Resistance-Max: 2R; Insulation Resistance-Min: 100MR; Channels: 2; Output Impedance: 120R; Current Rating: 100mA
R20 = CSS0402FT10L0: Fixed Resistor, Metal Alloy, 0.33W, 0.01ohm, 1% +/-Tol, 100ppm/Cel, Surface Mount, 0402; Manufacturer: Stackpole Electronics
R21 R22 = RP0402DRD07100RL: Res, 100R, 0.5%, 0.063W, Thin Film, 0402 Rohs Compliant: Yes; Manufacturer: Yageo
R28 = RC0402FR-7D3K3L: as R9 on sheet Power Supply
R30 = RC0402FR-7D33KL: Fixed Resistor, Metal Glaze/thick Film, 0.0625W, 33000ohm, 50V, 1% +/-Tol, 100ppm/Cel, Surface Mount, 0402; Manufacturer: Yageo
R31 R32 = RK73H1HRTTCM60R4F: Fixed Resistor, Metal Glaze/thick Film, 0.05W, 60.4ohm, 25V, 1% +/-Tol, 300ppm/Cel, Surface Mount, 0201; Manufacturer: KOA Speer
R43 = RP0402BRD0710KL: as R24 on sheet Microcontroller
U4 = INA193AQDBVRQ1: Operational Amplifier, 1 Func, PDSO5; Manufacturer: Texas Instruments; Package Body Material: Plastic; Adjustable Threshold: No; Throw Configuration: POWER SUPPLY SUPPORT CIRCUIT; Number of Channels: 1; Package Equivalence Code: TSOP5/6,.11,37; Power Supplies: 12V; Supply Current-Max (Isup): 1.25mA; Max Supply Voltage: 18V; Min Supply Voltage: 2.7V; Qualification Status: Not Qualified
U6 = TCAN1043DMTRQ1: Ethernet Transceiver, 1-Trnsvr, PDSO14; Manufacturer: Texas Instruments

## Sheet NTC.SchDoc
size A4; SheetNumber: 6; SheetTotal: 6
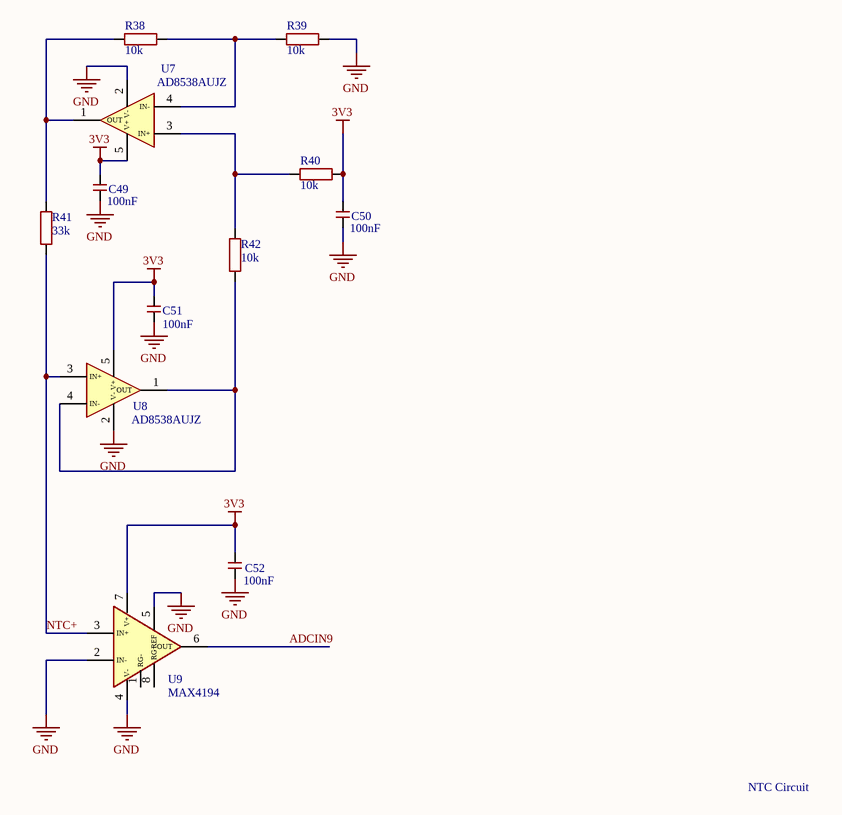
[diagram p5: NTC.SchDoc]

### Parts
C49  100nF  [C0402]
C50  100nF  [C0402]
C51  100nF  [C0402]
C52  100nF  [C0402]
R38  10k  [R0402]
R39  10k  [R0402]
R40  10k  [R0402]
R41  33k  [R0402]
R42  10k  [R0402]
U7  AD8538AUJZ  [SOT95P280X100-5N]
U8  AD8538AUJZ  [SOT95P280X100-5N]
U9  MAX4194  [SOIC127P600X175-8N]

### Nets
3V3: C49.2 C50.2 C51.2 C52.2 R40.2 U7.5(V+) U8.5(V+) U9.7(V+)
GND: C49.1 C50.1 C51.1 C52.1 R39.2 U7.2(V-) U8.2(V-) U9.2(IN-) U9.4(V-) U9.5(REF)
ADCIN9: U9.6(OUT)
NTC+: R41.1 U8.3(IN+) U9.3(IN+)
NetR38_1: R38.1 R41.2 U7.1(OUT)
NetR38_2: R38.2 R39.1 U7.4(IN-)
NetR40_1: R40.1 R42.2 U7.3(IN+)
NetR42_1: R42.1 U8.1(OUT) U8.4(IN-)

Not connected (* = marked no-connect by the designer): U9 1(RG-) 8(RG+)

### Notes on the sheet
- NTC Circuit

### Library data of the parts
C49-C52 = C0402C104K3PACTU: as C2 on sheet Power Supply
R38-R40 R42 = RP0402BRD0710KL: as R24 on sheet Microcontroller
R41 = RC0402FR-7D33KL: as R30 on sheet Shunt
U7 U8 = AD8538AUJZ-REEL7: Operational Amplifier, 1 Func, 30uV Offset-Max, CMOS, PDSO5; Manufacturer: Analog Devices; Package Body Material: Plastic; Architecture: VOLTAGE-FEEDBACK; Average Bias Current-Max (IIB): 100pA; Bias Current-Max (IIB) @25C: 25pA; Common-mode Reject Ratio-Nom: 135dB; Frequency Compensation: YES; Neg Supply Voltage Limit-Max: 0V; Channels: 1; Package Equivalence Code: TSOP5/6,.11,37; Power: No; Power Supplies: +-1.35/+-2.5/2.7/5V; Slew Rate: 0.4V/µs; Max Supply Current: 215uA; Supply Voltage Limit-Max: 6V; Nominal Supply Voltage: 5V; Time @ Peak Reflow Temperature-Max (s): 40s; Unity Gain BW-Nom: 430kHz; Voltage Gain-Min: 178000; Qualification Status: Not Qualified
U9 = MAX4194ESA+: Instrumentation Amplifier, 1 Func, 690uV Offset-Max, 0.25MHz Band Width, PDSO8; Manufacturer: Maxim; Package Body Material: Plastic; Average Bias Current-Max (IIB): 20nA; Bandwidth (3dB)-Nom: 250kHz; Common Mode Rejection Ratio-Min: 73dB; Input Offset Current-Max (IIO): 3nA; Channels: 1; Package Equivalence Code: SOP8,.25; Power Supplies: +-1.35/+-3.75/2.7/7.5V; Slew Rate: 0.06V/µs; Max Supply Current: 110uA; Supply Voltage Limit-Max: 8V; Nominal Supply Voltage: 5V; Time @ Peak Reflow Temperature-Max (s): 30s; Voltage Gain-Max: 10000; Qualification Status: Not Qualified

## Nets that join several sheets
3V3: Power Supply (R8.2), Microcontroller (17 pins), Shunt (C21.2 C37.2 U4.5 U6.5), NTC (8 pins)
5V: Power Supply (9 pins), Shunt (C46.2 U6.3)
12V: Input Stage (Q1.3), Power Supply (5 pins), Pump Driver (C16.2 U3.17), Shunt (C34.2 C39.1 R28.2 U6.10)
GND: Input Stage (14 pins), Power Supply (22 pins), Microcontroller (31 pins), Pump Driver (6 pins), Shunt (16 pins), NTC (10 pins)
ADCIN0: Microcontroller (U5.50), Pump Driver (C17.2 R17.1)
ADCIN1: Microcontroller (U5.49), Shunt (U4.1)
ADCIN9: Microcontroller (U5.48), NTC (U9.6)
CAN_N: Input Stage (J1.B1), Shunt (C53.1 D9.1 F1.3 R32.1)
CAN_P: Input Stage (J1.B2), Shunt (C54.2 D9.2 F1.2 R31.2)
EN: Microcontroller (U5.2), Shunt (U6.6)
~{FAULT}: Microcontroller (U5.8), Pump Driver (R11.1)
IN0: Microcontroller (U5.19), Pump Driver (R12.1)
IN1: Microcontroller (U5.22), Pump Driver (R13.1)
nFAULT: Microcontroller (U5.5), Shunt (U6.8)
nSTB: Microcontroller (U5.1), Shunt (U6.14)
NTC+: Input Stage (J1.A1), NTC (R41.1 U8.3 U9.3)
nTRST: Input Stage (J1.B8), Microcontroller (U5.76)
PUMP+: Pump Driver (5 pins), Shunt (R20.1 R21.2)
PUMP_OUT: Input Stage (J1.B3), Shunt (R20.2 R22.2)
RTCK: Input Stage (J1.B12), Microcontroller (U5.80)
RXD: Microcontroller (U5.63), Shunt (U6.4)
SEL0: Microcontroller (U5.9), Pump Driver (R15.1)
SEL1: Microcontroller (U5.10), Pump Driver (R16.1)
SEN: Microcontroller (U5.12), Pump Driver (R14.1)
TCK: Input Stage (J1.B11), Microcontroller (U5.79)
TDI: Input Stage (J1.B9), Microcontroller (U5.77)
TDO: Input Stage (J1.B10), Microcontroller (U5.78)
TMS: Input Stage (J1.B7), Microcontroller (U5.75)
TXD: Microcontroller (U5.62), Shunt (U6.1)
